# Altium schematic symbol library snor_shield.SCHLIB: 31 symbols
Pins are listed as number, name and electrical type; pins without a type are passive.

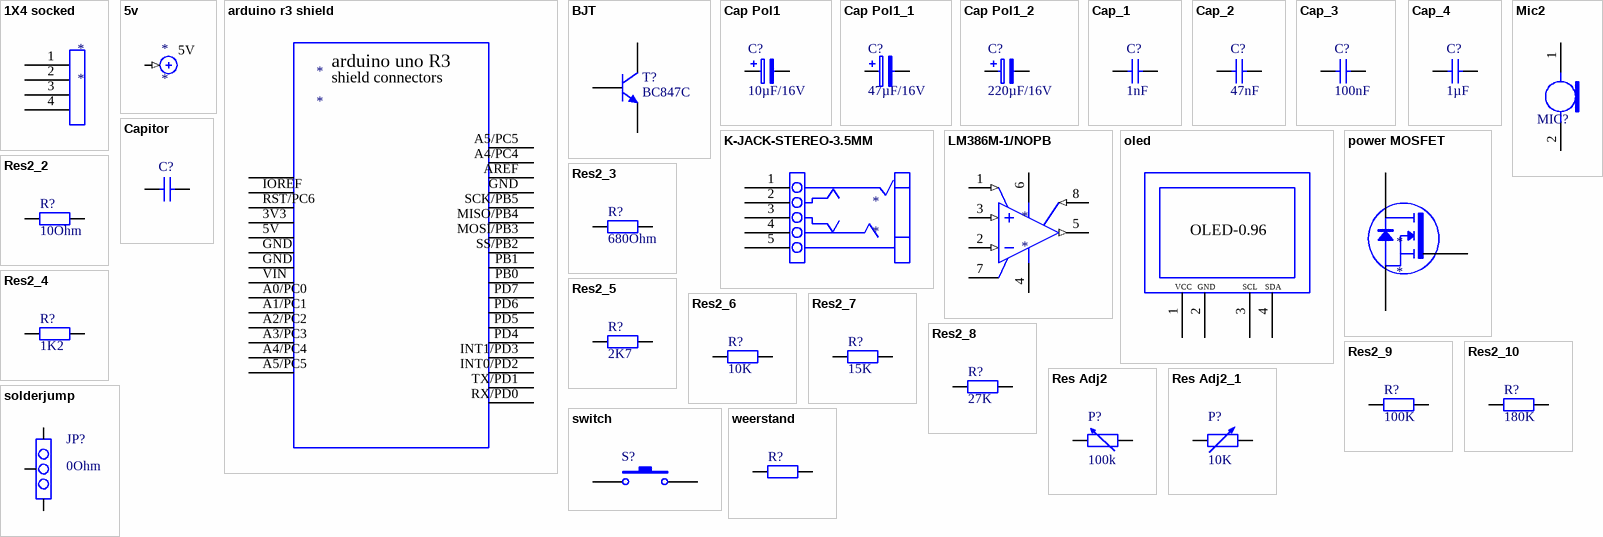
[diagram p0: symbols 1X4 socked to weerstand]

## 1X4 socked
designator *
footprint oled scherm
pins: 1 9, 2 10, 3 11, 4 12

## 5v
designator *
pins: 1 (in)

## arduino r3 shield
designator *
footprint arduino
pins: 3V3 26, 5V 27, ?1 23, A0/PC0 31, A1/PC1 32, A2/PC2 33, A3/PC3 34, A4/PC4 35, A4/PC4 38, A5/PC5 36, A5/PC5 37, AREF 39, GND 28, GND 29, GND 40, INT0/PD2 52, INT1/PD3 51, IOREF 24, MISO/PB4 42, MOSI/PB3 43, PB0 46, PB1 45, PD4 50, PD5 49, PD6 48, PD7 47, RST/PC6 25, RX/PD0 54, SCK/PB5 41, SS/PB2 44, TX/PD1 53, VIN 30

## BJT
designator T?, comment BC847C
NPN General Purpose Amplifier
simulation model 2N3904 (NPN)
signal-integrity model 2N3904
footprint bipolar BjT
pins: 1 E, 2 B, 3 C

## Cap Pol1
designator C?  value 10µF/16V  (hidden comment: Cap Pol1)
Polarized Capacitor (Radial) 10µF
simulation model CAP (Capacitor)
signal-integrity model Cap Pol
footprint elecktor trans 1
pins: 1, 2
1 alternate drawing of the same symbol

## Cap Pol1_1
designator C?, comment value 47µF/16V  (hidden comment: Cap Pol1)
Polarized Capacitor (Radial) 47µF
simulation model CAP (Capacitor)
signal-integrity model Cap Pol
footprint elektor trans 2
pins: 1, 2
1 alternate drawing of the same symbol

## Cap Pol1_2
designator C?, comment value 220µF/16V  (hidden comment: Cap Pol1)
Polarized Capacitor (Radial) 220µF
simulation model CAP (Capacitor)
signal-integrity model Cap Pol
footprint elektor trans 3
pins: 1, 2
1 alternate drawing of the same symbol

## Cap_1
designator C?, comment value 1nF  (hidden comment: Cap)
Capacitor
simulation model CAP (Capacitor)
signal-integrity model Cap
footprint SMD 0805
pins: 1, 2

## Cap_2
designator C?, comment value 47nF  (hidden comment: Cap)
Capacitor
simulation model CAP (Capacitor)
signal-integrity model Cap
footprint SMD 0805
pins: 1, 2

## Cap_3
designator C?, comment value 100nF  (hidden comment: Cap)
Capacitor
simulation model CAP (Capacitor)
signal-integrity model Cap
footprint SMD 0805
pins: 1, 2

## Cap_4
designator C?, comment value 1µF  (hidden comment: Cap)
Capacitor
simulation model CAP (Capacitor)
signal-integrity model Cap
footprint SMD 0805
pins: 1, 2

## Capitor
designator C?, comment Cap  (value not drawn)
Capacitor
simulation model CAP (Capacitor)
signal-integrity model Cap
footprint SMD 0805
pins: 1, 2

## K-JACK-STEREO-3.5MM
designator *
footprint adioplug3.5mm
pins: 1, 2, 3, 4, 5

## LM386M-1/NOPB
designator *
footprint LM386M-1/NOPB
pins: 1 GAIN (in), 2 IN- (in), 3 IN+ (in), 4 GND (power), 5 VOUT (out), 6 VS (power), 7 BYPASS, 8 GAIN (in)

## Mic2
designator MIC?  (value not drawn)
Microphone
footprint Electret Condenser Microphone
pins: 1, 2

## oled
designator ?
footprint oled scherm
pins: 1 VCC, 2 GND, 3 SCL, 4 SDA

## power MOSFET
designator *
footprint power mosfet
pins: 6, 7, 8

## Res2_2
designator R?, comment value 10Ohm  (hidden comment: Res2)
Resistor
simulation model RESISTOR (Resistor)
signal-integrity model Res
footprint SMD 0805
pins: 1, 2

## Res2_3
designator R?, comment value 680Ohm  (hidden comment: Res2)
Resistor
simulation model RESISTOR (Resistor)
signal-integrity model Res
footprint SMD 0805
pins: 1, 2

## Res2_4
designator R?, comment value 1K2  (hidden comment: Res2)
Resistor
simulation model RESISTOR (Resistor)
signal-integrity model Res
footprint SMD 0805
pins: 1, 2

## Res2_5
designator R?, comment value 2K7  (hidden comment: Res2)
Resistor
simulation model RESISTOR (Resistor)
signal-integrity model Res
footprint SMD 0805
pins: 1, 2

## Res2_6
designator R?, comment value 10K  (hidden comment: Res2)
Resistor
simulation model RESISTOR (Resistor)
signal-integrity model Res
footprint SMD 0805
pins: 1, 2

## Res2_7
designator R?, comment value 15K  (hidden comment: Res2)
Resistor
simulation model RESISTOR (Resistor)
signal-integrity model Res
footprint SMD 0805
pins: 1, 2

## Res2_8
designator R?, comment value 27K  (hidden comment: Res2)
Resistor
simulation model RESISTOR (Resistor)
signal-integrity model Res
footprint SMD 0805
pins: 1, 2

## Res2_9
designator R?, comment value 100K  (hidden comment: Res2)
Resistor
simulation model RESISTOR (Resistor)
signal-integrity model Res
footprint SMD 0805
pins: 1, 2

## Res2_10
designator R?, comment value 180K  (hidden comment: Res2)
Resistor
simulation model RESISTOR (Resistor)
signal-integrity model Res
footprint SMD 0805
pins: 1, 2

## Res Adj2
designator P?  value 100k  (hidden comment: Res Adj2)
Variable Resistor 10K; Set Position: 0.5
simulation model VRES (Variable Resistor)
signal-integrity model Res Adj
footprint potmeter
pins: 1, 2, 3

## Res Adj2_1
designator P?, comment value 10K  (hidden comment: Res Adj2)
Variable Resistor; Set Position: 0.5
simulation model VRES (Variable Resistor)
signal-integrity model Res Adj
footprint potmeter
pins: 1, 2, 3

## solderjump
designator JP?, comment value 0Ohm  (hidden comment: Res2)
Resistor
simulation model RESISTOR (Resistor)
signal-integrity model Res
footprint soldeer_jumper
pins: 14, 15, 17

## switch
designator S?, comment SW-PB  (value not drawn)
Switch
footprint switch
pins: 1, 2

## weerstand
designator R?, comment Res2  (value not drawn)
Resistor
simulation model RESISTOR (Resistor)
signal-integrity model Res
footprint SMD 0805
pins: 1, 2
